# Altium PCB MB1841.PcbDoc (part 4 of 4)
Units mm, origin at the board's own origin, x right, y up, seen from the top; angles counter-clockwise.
Board outline 70 x 82.5 mm, 4 copper layers (Top Layer, Signal Layer 1, Signal Layer 2, Bottom Layer), stack 1.49 mm thick; 252 components, 169 nets, 1058 pads, 796 vias.
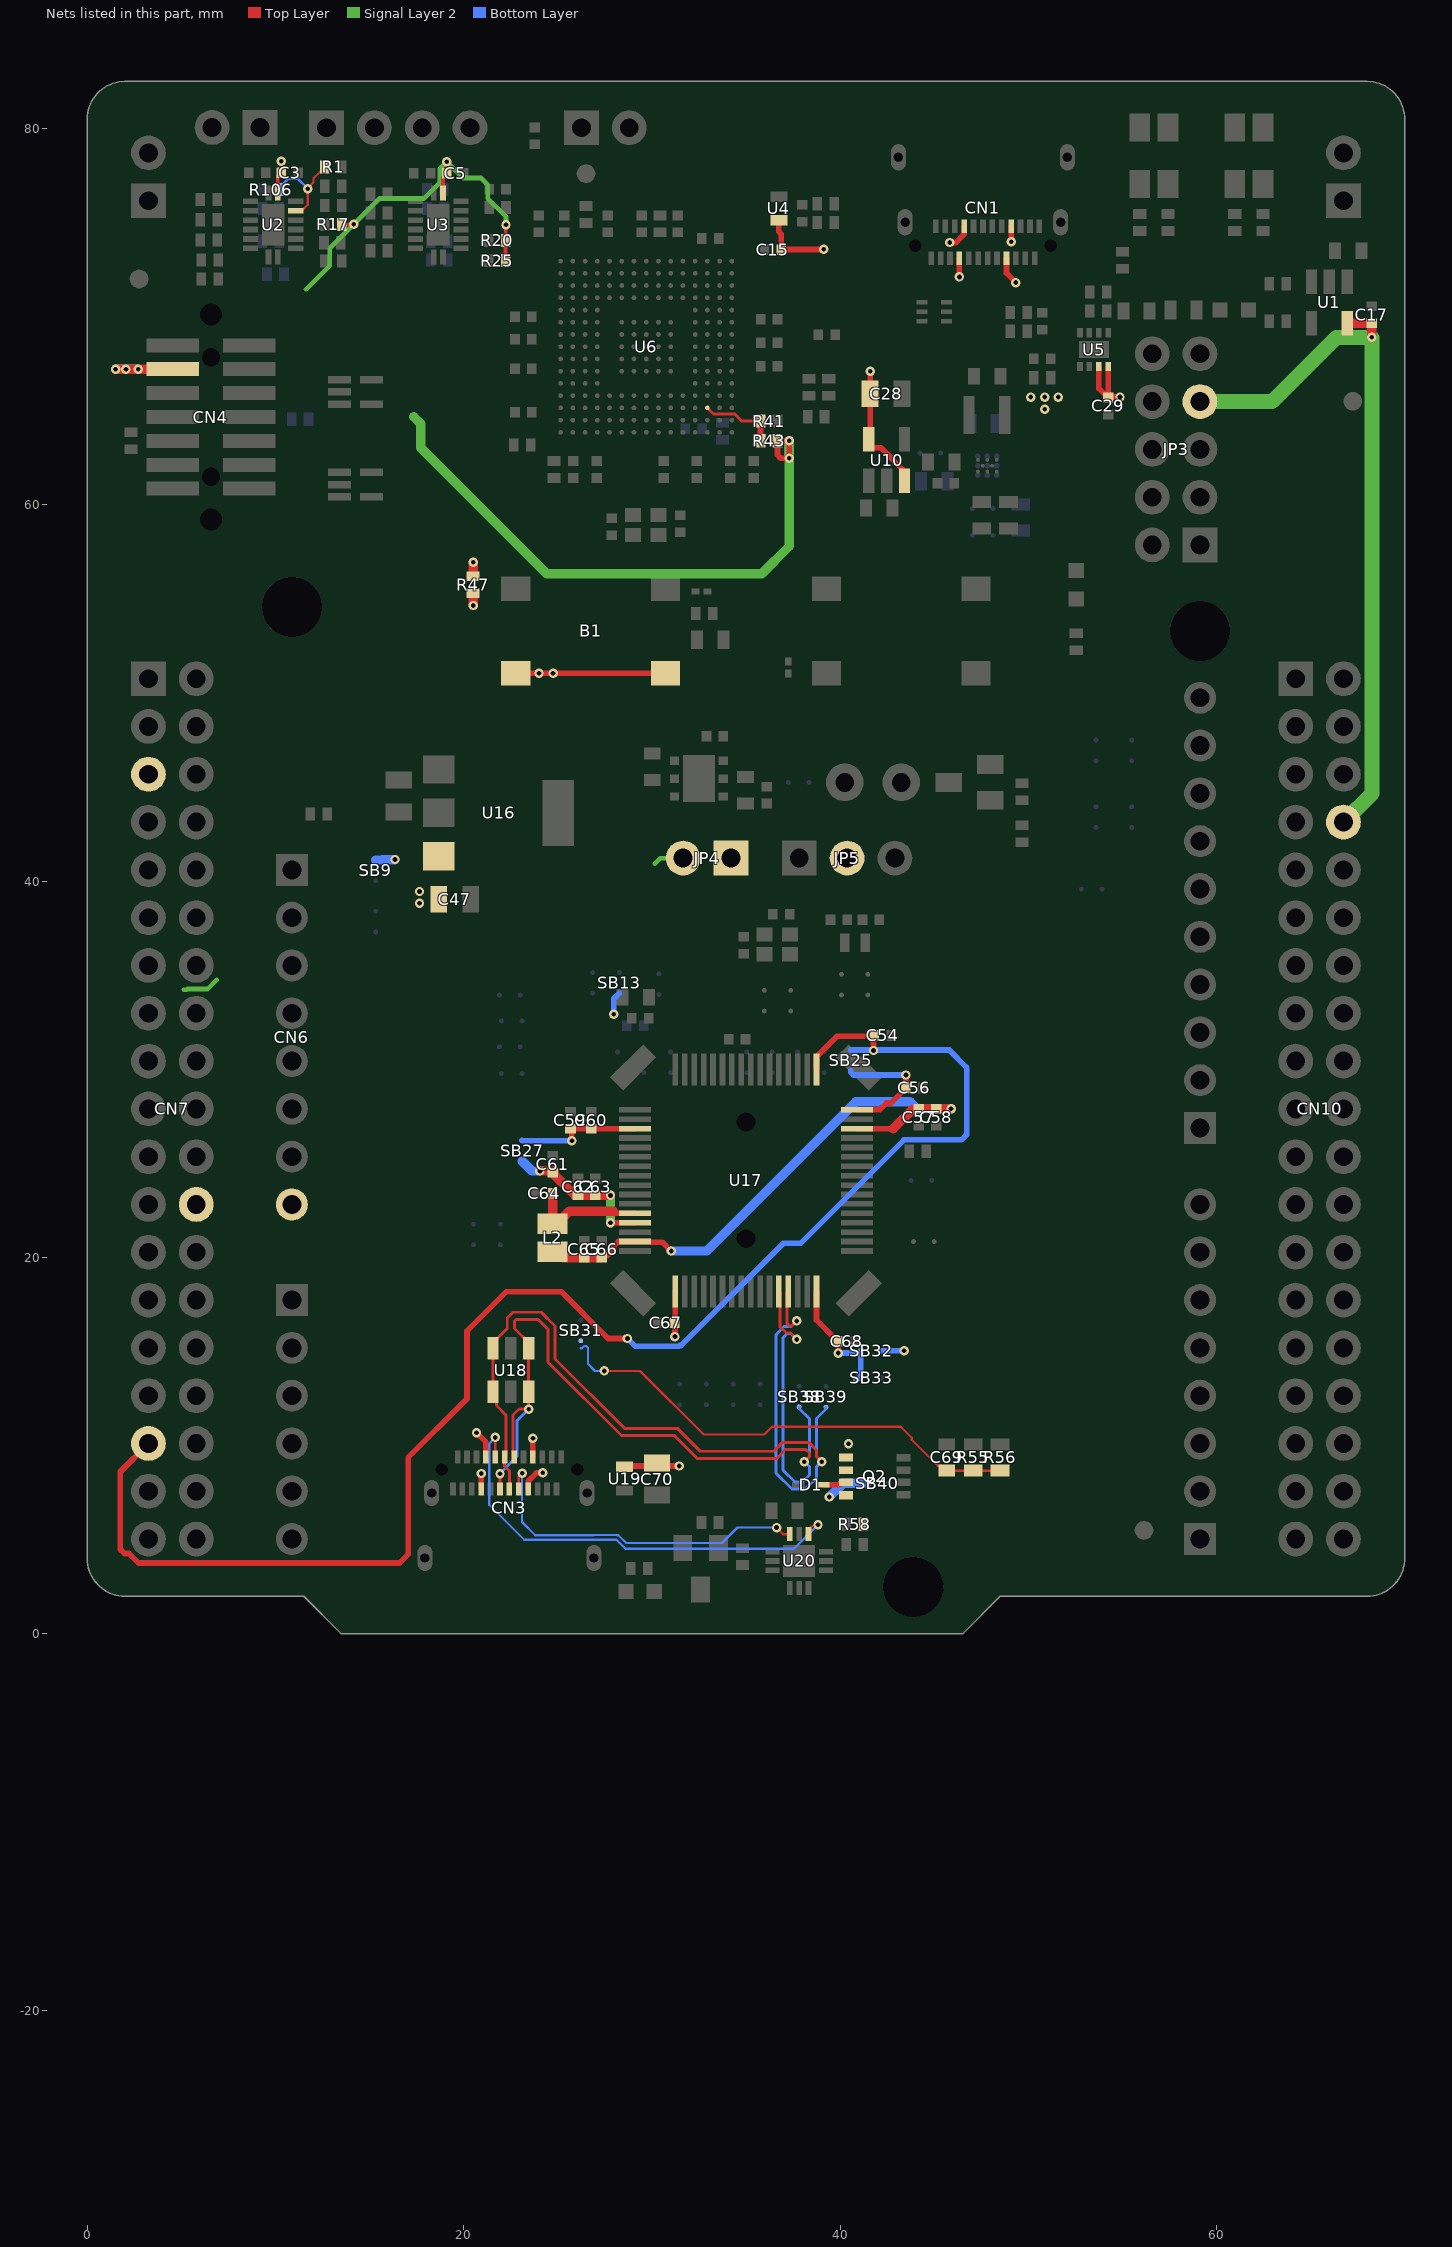
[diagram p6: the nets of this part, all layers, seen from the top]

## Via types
v1: diameter 0.5, hole 0.25, Top Layer to Bottom Layer, tented both sides, 796 vias

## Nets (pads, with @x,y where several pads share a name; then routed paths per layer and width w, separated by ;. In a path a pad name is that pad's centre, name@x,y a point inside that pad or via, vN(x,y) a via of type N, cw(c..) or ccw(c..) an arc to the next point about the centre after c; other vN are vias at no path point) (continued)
T_VCC: C3.1 C5.2 R17.2 R20.2 R25.2 R43.2 R47.2 U2.16 U3.16 | length 57.5
  Top Layer w0.2: U2.16@10.125,76.575 10.125,77.475 C3.1@10.3,77.65 v1(10.3,78.25) ; R17.2@13.525,74.9 v1(14.15,74.9) ; U3.16@18.9,76.575 18.9,77.4 19.1,77.6 C5.2@19.1,77.625 v1(19.1,78.225) ; R25.2@22.225,72.975 R20.2@22.225,74.05 22.238,74.063 22.238,74.862 v1(22.25,74.875)
  Top Layer w0.3: 36.675,62.65 R43.2@36.675,63.4 v1(37.3,63.4) v1(37.3,62.475) 36.85,62.475 36.675,62.65
  Top Layer w0.5: R47.2@20.5,56.2 v1(20.5,56.95)
  Signal Layer 2 w0.25: 11.625,71.45 12.875,72.7 12.875,73.625 v1(14.15,74.9) 15.525,76.275 17.875,76.275 18.725,77.125 18.725,77.85 v1(19.1,78.225) 19.955,77.37 20.915,77.37 21.275,77.01 21.275,76.275 22.25,75.3 v1(22.25,74.875)
  Signal Layer 2 w0.5: 17.35,64.675 17.725,64.3 17.725,63.025 24.425,56.325 35.825,56.325 37.3,57.8 v1(37.3,62.475) v1(37.3,63.4)
  Bottom Layer w0.5: v1(37.3,62.475) v1(37.3,63.4)
T_VCC_AIN: R41.1 R43.1 U6.N3 | length 4.2
  Top Layer w0.15: U6.N3@32.95,65.15 33.28,64.82 34.405,64.82 34.775,64.45 R41.1@35.775,64.45
  Top Layer w0.3: R43.1@35.775,63.4 R41.1@35.775,64.45
UCPD_CC1_C: CN3.A5 U20.7 | length 24.6
  Top Layer w0.12: CN3.A5@21.678,9.396 v1(21.678,10.441) ; U20.7@38.325,5.3 38.415,5.39 38.415,5.64 38.516,5.741 38.766,5.741 v1(38.825,5.8)
  Bottom Layer w0.12: v1(21.678,10.441) 21.361,10.124 21.361,6.858 23.216,5.004 28.118,5.004 28.597,4.525 37.55,4.525 v1(38.825,5.8)
UCPD_CC2_C: CN3.B5 U20.9 | length 18.7
  Top Layer w0.12: CN3.B5@22.928,7.696 22.928,8.358 v1(23.105,8.534) ; v1(36.625,5.65) 36.975,5.3 U20.9@37.325,5.3
  Bottom Layer w0.12: v1(23.105,8.534) 23.105,5.947 23.808,5.244 26.885,5.244 26.899,5.258 28.143,5.258 28.157,5.244 28.217,5.244 28.635,4.826 33.726,4.826 34.55,5.65 v1(36.625,5.65)
USB_FS_N: CN3.A7 CN3.B7 SB38.2 U17.44 U18.1 U18.6 | length 50.7
  Top Layer w0.155: CN3.B7@21.928,7.696 v1(21.928,8.517) ; CN3.A7@22.678,9.396 22.619,9.456 22.619,9.979 22.619,11.633 22.931,11.946 v1(23.454,11.946) U18.6@23.454,12.871 U18.1@23.454,15.171 23.454,15.471 22.695,16.23 22.695,16.622 22.786,16.713 23.96,16.713 24.47,16.203 24.47,14.455 28.381,10.544 31.192,10.544 32.411,9.325 36.633,9.325 37.108,9.8 38.175,9.8 38.369,9.606 38.369,9.431 v1(38.094,9.156) ; U17.44@36.75,18.2 36.81,18.14 36.81,16.32 37.147,15.983 37.367,15.983 v1(37.7,15.65)
  Bottom Layer w0.155: v1(21.928,8.517) 22.835,9.423 22.835,11.326 v1(23.454,11.946) ; v1(37.7,15.65) 37.4,15.95 37.184,15.95 36.975,15.741 36.975,8.7 37.6,8.075 37.994,8.075 38.369,8.45 38.369,8.749 38.369,8.881 v1(38.094,9.156) 38.369,9.431 38.369,10.021 38.369,11.431 37.843,11.957 37.843,12.045 SB38.2@37.824,12.064
USB_FS_P: CN3.A6 CN3.B6 SB39.2 U17.45 U18.3 U18.4 | length 49.7
  Top Layer w0.155: CN3.B6@22.428,7.696 22.428,8.65 22.178,8.9 CN3.A6@22.178,9.396 22.238,9.456 22.238,10.137 22.238,11.633 21.737,12.134 21.737,12.689 U18.4@21.554,12.871 U18.3@21.554,15.171 21.554,15.471 22.314,16.23 22.314,16.782 22.626,17.094 24.118,17.094 24.851,16.361 24.851,14.613 28.539,10.925 31.35,10.925 32.569,9.706 36.475,9.706 36.95,10.181 38.333,10.181 38.75,9.764 38.75,9.431 v1(39.025,9.156) ; U17.45@37.25,18.2 37.191,18.14 37.191,16.478 37.304,16.364 37.433,16.364 v1(37.7,16.631)
  Bottom Layer w0.155: v1(37.7,16.631) 37.4,16.331 37.026,16.331 36.594,15.899 36.594,8.542 37.442,7.694 38.152,7.694 38.75,8.292 38.75,8.591 38.75,8.881 v1(39.025,9.156) 38.75,9.431 38.75,10.179 38.75,11.45 39.231,11.931 39.231,12.031 SB39.2@39.25,12.05
V11: C57.2 C58.2 C65.2 C66.2 L2.1 U17.31 U17.62 | length 30.8
  Top Layer w0.3: C66.2@27.325,20 27.43,20.105 27.625,20.105 27.98,20.46 27.98,20.612 28.218,20.85 U17.31@29.1,20.85 29.888,20.85 29.926,20.812 30.563,20.812 v1(31.025,20.35) ; U17.62@40.9,26.85 42.825,26.85
  Top Layer w0.5: L2.1@24.725,20.3 24.975,20.3 25.28,19.995 26.395,19.995 C65.2@26.4,20 26.405,19.995 27.32,19.995 C66.2@27.325,20 ; 42.825,26.85 43.87,27.895 44.17,27.895 C57.2@44.175,27.9 C58.2@45.1,27.9 v1(45.9,27.9)
  Bottom Layer w0.5: v1(31.025,20.35) 32.912,20.35 40.833,28.27 43.73,28.27 44.1,27.9 v1(45.9,27.9)
VBAT: C54.2 CN7.33 SB25.2 U17.1 | length 83.6
  Top Layer w0.3: CN7.33@3.25,10.12 1.75,8.62 1.75,4.5 1.975,4.275 2.212,4.275 2.722,3.765 16.59,3.765 17.05,4.225 17.05,9.375 20.175,12.5 20.175,16.1 22.265,18.19 25.185,18.19 27.675,15.7 v1(28.7,15.7) ; U17.1@38.75,30 38.75,30.7 38.775,30.7 39.825,31.75 C54.2@41.775,31.75 ; v1(41.775,31) C54.2@41.775,31.75 ; C54.2@41.825,31.8 C54.2@41.775,31.75
  Bottom Layer w0.3: v1(28.7,15.7) 29.12,15.28 31.44,15.28 31.485,15.325 31.55,15.325 36.98,20.755 37.905,20.755 43.4,26.25 46.45,26.25 46.725,26.525 46.725,30.1 45.8,31.025 SB25.2@40.56,31.025
VBUS_C: C70.2 CN3.A4 CN3.A9 CN3.B4 CN3.B9 D1.1 Q2.5 Q2.6 Q2.7 Q2.8 R58.1 SB40.2 U19.1 | length 11.2
  Top Layer w0.3: v1(20.678,10.691) 21.178,10.191 CN3.A4@21.178,9.396 ; CN3.B9@20.928,7.696 v1(20.928,8.526) ; CN3.B4@23.428,7.696 23.428,8.123 23.865,8.56 v1(24.197,8.56) ; CN3.A9@23.678,9.396 v1(23.678,10.391) ; U19.1@28.55,8.875 28.6,8.925 v1(31.45,8.925) ; D1.1@39.125,7.925 40.025,7.925 40.15,8.05 Q2.7@40.325,8.05
  Bottom Layer w0.5: v1(39.425,7.275) 40.15,8 SB40.2@41.425,8
  other v1: 40.45,10.1
VBUS_SENSE: C69.2 R55.2 R56.1 SB31.1 | length 26
  Top Layer w0.12: v1(27.475,13.975) 29.375,13.975 32.75,10.6 35.975,10.6 36.385,11.01 43.223,11.01 43.805,10.428 43.805,10.32 45.19,8.935 45.415,8.935 C69.2@45.675,8.675 R55.2@47.075,8.675 R56.1@48.5,8.675
  Bottom Layer w0.12: 26.225,15.175 26.275,15.175 26.4,15.3 26.5,15.3 26.6,15.2 26.6,14.35 26.975,13.975 v1(27.475,13.975)
VBUS_STLK: C15.1 C17.2 C28.2 C29.2 CN1.A4 CN1.A9 CN1.B4 CN1.B9 CN10.8 JP3.7 U1.5 U4.1 U5.3 U5.4 U10.3 U10.5 | length 58
  Top Layer w0.3: U4.1@36.75,75.125 36.75,74.5 36.875,74.375 C15.1@36.875,73.55 36.887,73.562 39.112,73.562 v1(39.125,73.575) ; U10.5@41.525,63.475 41.6,63.55 C28.2@41.6,65.9 v1(41.6,67.1) ; U10.5@41.63,63.179 41.78,63.029 42.171,63.029 43.38,61.82 U10.3@43.38,61.425 ; v1(45.823,73.939) 46.154,73.939 46.592,74.377 CN1.B4@46.592,74.803 ; v1(46.342,72.108) CN1.A9@46.342,73.103 ; CN1.A4@48.842,73.103 48.842,72.308 v1(49.342,71.808) ; v1(49.092,73.973) CN1.B9@49.092,74.803 ; U5.3@53.75,67.35 53.75,66.175 54.125,65.8 C29.2@54.125,65.725 ; C29.2@54.175,65.725 v1(54.875,65.725) ; U5.4@54.25,67.35 54.25,65.85 C29.2@54.275,65.825
  Top Layer w0.5: U1.5@66.95,69.65 C17.2@68.25,69.65 ; v1(68.25,68.9) C17.2@68.25,69.65 ; C17.2@68.275,69.65 C17.2@68.25,69.65
  Signal Layer 2 w0.8: JP3.7@59.125,65.485 62.96,65.485 66.374,68.899 v1@68.249,68.899 ; CN10.8@66.75,43.14 68.275,44.665 68.275,68.875 v1(68.25,68.9)
  other v1: 50.87,65.075 50.125,65.725 50.875,65.725 51.6,65.725
VCP_RX_BP: R1.1 R106.2 U2.14 | length 5.2
  Top Layer w0.12: U2.14@11.075,75.625 11.165,75.715 11.49,75.715 11.72,75.945 v1(11.72,76.795) ; v1@11.68,76.795 12.025,77.14 12.025,77.35 12.345,77.67 12.43,77.67 12.625,77.865 R1.1@12.625,77.95
  Bottom Layer w0.12: R106.2@10.2,76.75 10.2,76.845 10.67,77.315 11.2,77.315 11.67,76.845 v1@11.71,76.845
VDD: B1.1 B1.2 CN4.3 CN7.5 JP4.1 JP5.2 R47.1 SB9.1 | length 15
  Top Layer w0.3: B1.1@22.77,51.05 v1(24,51.05) v1(24.75,51.05) ; v1@24.8,51.075 24.825,51.05 B1.2@30.72,51.05
  Top Layer w0.5: v1(1.5,67.195) v1(2.05,67.195) v1(2.7,67.195) CN4.3@4.528,67.195 ; v1(20.5,54.65) R47.1@20.5,55.3
  Signal Layer 2 w0.5: v1(1.5,67.195) v1(2.05,67.195) v1(2.7,67.195)
  Bottom Layer w0.5: v1(1.5,67.195) v1(2.05,67.195) v1(2.7,67.195) ; SB9.1@15.325,41.125 15.652,41.125 15.672,41.145 16.345,41.145 v1(16.35,41.15)
VDD_MCU: C56.2 C59.2 C60.2 C67.2 JP4.2 SB13.1 SB25.1 SB27.1 SB32.1 U17.19 U17.33 U17.64 | length 20.3
  Top Layer w0.3: v1(25.75,26.2) 25.75,26.75 25.66,26.84 26.76,26.84 26.77,26.85 C60.2@26.775,26.85 U17.19@29.1,26.85 ; v1(31.225,15.8) 31.225,16.5 C67.2@31.2,16.525 31.25,16.575 U17.33@31.25,18.2 ; U17.64@40.9,27.85 42.1,27.85 42.462,28.212 42.712,28.212 C56.2@43.38,28.88 ; C56.2@43.493,29.01 C56.2@43.493,28.993 ; v1(43.5,29.7) 43.5,29 C56.2@43.493,28.993 ; C56.2@43.38,28.88 C56.2@43.493,28.993 ; C56.2@43.38,28.88 43.388,28.88 43.493,28.985 C56.2@43.493,28.993
  Signal Layer 2 w0.25: 30.15,40.925 30.45,41.225 JP4.2@31.66,41.225
  Bottom Layer w0.3: SB27.1@23.1,26.225 23.125,26.2 v1(25.75,26.2) ; v1(27.975,32.925) 27.975,33.75 SB13.1@28.275,34.05 ; SB25.1@40.56,29.925 40.56,29.85 40.71,29.7 v1(43.5,29.7) ; SB32.1@42.2,15.05 v1(43.4,15.05)
VDDSMPS: C61.2 C62.2 C63.2 SB27.2 U17.29 | length 8.3
  Top Layer w0.3: v1@27.833,21.85 U17.29@29.1,21.85
  Top Layer w0.5: v1(24.05,24.6) 24.056,24.606 C61.2@24.79,24.606 ; C61.2@24.815,24.606 24.82,24.601 24.82,24.388 25.633,23.575 25.903,23.305 26.095,23.305 26.1,23.3 C63.2@27,23.3 27.025,23.3 v1(27.8,23.3)
  Signal Layer 2 w0.5: v1(27.8,21.85) v1(27.8,23.3)
  Bottom Layer w0.5: SB27.2@23.1,25.125 23.625,24.6 v1(24.05,24.6)
VDDUSB: C68.2 SB32.2 SB33.2 U17.48 | length 6.6
  Top Layer w0.3: U17.48@38.75,18.2 38.75,16.675 C68.2@39.745,15.68 ; v1(39.9,14.925) C68.2@39.9,15.55
  Bottom Layer w0.3: v1(39.9,14.925) 40.975,14.925 SB32.2@41.1,15.05 SB33.2@41.1,13.625 41.07,13.595 40.925,13.595 40.83,13.5
VIN: C47.2 CN6.8 CN7.24 U16.3 | length 2
  Signal Layer 2 w0.25: 5.125,34.225 5.267,34.225 5.312,34.27 6.395,34.27 6.875,34.75
  other v1: 17.65,38.825 17.65,39.45
VLX: C64.2 L2.2 U17.28 | length 5.9
  Top Layer w0.3: 27.95,22.47 28.07,22.35 U17.28@29.1,22.35
  Top Layer w0.5: L2.2@24.725,21.975 25.15,21.975 25.275,22.1 25.275,22.132 25.613,22.47 27.95,22.47 ; L2.2@24.725,22.2 C64.2@24.725,23.425
pads on no net: CN1.0 CN1.A2 CN1.A3 CN1.A8 CN1.A10 CN1.A11 CN1.B2 CN1.B3 CN1.B8 CN1.B10 CN1.B11 CN3.0 CN3.A2 CN3.A3 CN3.A8 CN3.A10 CN3.A11 CN3.B2 CN3.B3 CN3.B8 CN3.B10 CN3.B11 CN4.0 CN4.1 CN4.2 CN7.9 CN7.10 CN7.11 CN7.21 CN7.26 CN10.1 CN10.6 CN10.10 CN10.16 CN10.18 CN10.34 CN10.38 Designator1.1 Designator2.1 Designator3.1 U6.A1 U6.A2 U6.A3 U6.A4 U6.A5 U6.A8 U6.A9 U6.A11 U6.A12 U6.A13 U6.B1 U6.B2 U6.B3 U6.B4 U6.B5 U6.B6 U6.B7 U6.B8 U6.B9 U6.B10 U6.B11 U6.B12 U6.B13 U6.B14 U6.B15 U6.C2 U6.C3 U6.C12 U6.C13 U6.C14 U6.C15 U6.D1 U6.D2 U6.D3 U6.D11 U6.D13 U6.D14 U6.E1 U6.E2 U6.E3 U6.E4 U6.E12 U6.E13 U6.E14 U6.E15 U6.F1 U6.F4 U6.F14 U6.G4 U6.G14 U6.G15 U6.H2 U6.H3 U6.H4 U6.H14 U6.J3 U6.J4 U6.K1 U6.K2 U6.K3 U6.K12 U6.K13 U6.K14 U6.K15 U6.L1 U6.L12 U6.L13 U6.L14 U6.L15 U6.M2 U6.M3 U6.M4 U6.M7 U6.M12 U6.M13 U6.M14 U6.M15 U6.N2 U6.N4 U6.N6 U6.N7 U6.N11 U6.N13 U6.N14 U6.N15 U6.P2 U6.P4 U6.P5 U6.P6 U6.P7 U6.P8 U6.P9 U6.P10 U6.P11 U6.P12 U6.P13 U6.P14 U6.P15 U6.R2 U6.R6 U6.R7 U6.R8 U6.R9 U6.R10 U6.R11 U6.R12 U6.R13 U8.4 U10.4 U11.4 U12.E1 U15.3 U15.5 U17.0 U18.5 U22.C1

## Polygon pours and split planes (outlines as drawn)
GND on Top Layer "GND" (solid, remove dead copper, pour order 138): 68.45,84.375 70.175,82.65 70.175,2.125 66.85,-1.2 0.925,-1.2 -1.825,1.55 -1.825,82.05 0.5,84.375
5V_UCPD on Top Layer "NO_FT" (solid, pour order 125): 44.276,6.9 44.6,7.224 44.613,8.863 44.375,9.1 43.15,9.1 42.8,8.75 42.8,7 42.9,6.9
VBUS_C on Top Layer "NO_FT" (solid, pour order 124): 41.91,10.4 42.35,9.96 42.35,6.325 41.5,5.475 40.975,5.475 40.775,5.675 40.775,6.225 40.35,6.65 39.325,6.65 38.775,7.2 38.775,8.075 38.925,8.225 39.8,8.225 39.95,8.375 39.95,10.3 40.05,10.4
5V on Top Layer "NO_FT" (solid, pour order 113): 34.125,46.875 33.61,46.875 33.5,47 33.5,48.3 34.05,48.85 34.65,48.85 34.849,48.651 34.849,47.599
VIN on Top Layer "NO_FT" (solid, remove dead copper, pour order 8): 20.5,42.125 20.625,42 20.625,38.025 20.35,37.75 17.1,37.75 16.75,38.1 16.75,41.85 17.025,42.125
GND on Top Layer "NO_FT" (solid, remove dead copper, pour order 6): 20.625,45.025 20.35,44.75 16.15,44.75 15.875,45.025 15.875,48.2 16.275,48.6 20.275,48.6 20.625,48.25
5V_VIN on Top Layer "NO_FT" (solid, remove dead copper, pour order 4): 12.725,42.375 12.35,42.75 12.35,44.025 12.825,44.5 16.3,44.5 20.4,44.5 21,45.1 21,46.925 21.425,47.35 26.8,47.35 27.3,46.85 27.3,40.7 26.725,40.125 21.7,40.125 21.225,40.6 21.225,41.825 20.675,42.375
NetC44_2 on Top Layer "NO_FT" (solid, pour order 121): 33.3,43.9 33.85,43.35 37.625,43.35 38.05,43.775 38.05,44.4 37.725,44.725 34.45,44.725 34.225,44.95 33.375,44.95 33.3,44.875
5V_SMPS_IN on Top Layer "5V_SMPS_IN" (solid, pour order 126): 47.45,62.4 46.45,63.4 46.05,63.4 45.675,63.025 45.675,59.025 46.4,58.3 47.95,58.3 48.075,58.425 48.075,59.2 47.925,59.35 47.15,59.35 46.595,59.905 46.595,61.789 46.806,62 47.575,62
5V_VIN on Top Layer "5V_VIN_L01_P130" (solid, remove dead copper, pour order 130): 58.598,59.175 57.513,58.09 51.185,58.09 50.1,59.175 49.525,59.75 49.525,62.275 49.775,62.525 53.578,62.525 54.651,61.453 59.502,61.453 60.02,60.935 60.02,60.02 59.175,59.175
E5V on Top Layer "E5V_L01_P136" (solid, remove dead copper, pour order 136): 53.583,62.8 54.93,61.453 59.7,61.453 60.655,62.408 60.655,63.652 60.376,63.932 55.753,63.932 54.635,65.05 53.3,65.05 52.775,64.525 49.775,64.525 49.5,64.25 49.5,63.05 49.75,62.8
VBUS_STLK on Top Layer "VBUS_STLK_L01_P137" (solid, remove dead copper, pour order 137): 60.449,67.125 57.485,67.125 56.002,68.608 50.358,68.608 49.75,68 49.75,65.5 50.45,64.8 52.55,64.8 53.167,65.417 54.649,65.417 56.007,64.059 60.147,64.059 60.875,64.787 60.875,66.699
GND on Top Layer "GND_L01_P002" (solid, remove dead copper, pour order 2): 31.675,77.625 33.25,76.05 33.25,71.275 34.15,70.375 38.15,70.375 40,72.225 40,82.5 30.65,82.5 30.65,78.675 31.675,77.65
5V_STLK on Top Layer "5V_STLK_L01_P078" (solid, remove dead copper, pour order 78): 61.5,74 61.75,74.25 66.5,74.25 66.5,73 63.5,73 63.5,72.5 54.175,72.5 54.175,74
GND on Bottom Layer "GND" (solid, remove dead copper, pour order 134): 69.929,84.391 71.654,82.666 71.654,2.141 68.329,-1.184 2.404,-1.184 -0.346,1.566 -0.346,82.066 1.979,84.391
5V_SMPS_IN on Bottom Layer "5V_SMPS_IN" (solid, pour order 127): 46.405,63.42 46.405,63.625 46.255,63.775 45.2,63.775 45.1,63.675 45.1,63.375 45.25,63.225 45.25,62.85 44.95,62.55 44.65,62.55 44.225,62.125 44.075,62.125 43.775,61.825 43.775,60.73 43.905,60.6 44.745,60.6 45,60.855 45,61.875 45.25,62.125 46.925,62.125 47.025,62.225 47.025,62.8
VBUS_C on Bottom Layer "VBUS_C" (solid, remove dead copper, pour order 133): 40.275,10.425 40.951,10.424 42.175,9.2 42.175,8.5 41.675,8 42.175,7.5 42.175,7.075 41.951,6.851 39.424,6.851 39.175,7.1 39.175,7.375 40.075,8.275 40.075,10.225
5V_UCPD on Bottom Layer "5V_UCPD" (solid, remove dead copper, pour order 132): 44.289,6.913 44.6,7.224 44.6,8.85 44.35,9.1 43.025,9.1 42.425,8.5 42.425,7.5 43.012,6.913
NetR63_2 on Bottom Layer "NetR46_2" (solid, pour order 131): 45.45,62.05 46.95,62.05 47.15,62.25 47.4,62.25 47.525,62.125 47.525,60.925 47.2,60.6 47.2,59.375 47.125,59.3 45.775,59.3 45.225,59.85 45.225,61.825
VDD on Bottom Layer "VDD" (solid, pour order 123): 23.275,51.3 24,52.025 30.725,52.025 35.925,46.825 35.925,40.298 35.127,39.5 33.175,39.5 32.5,40.175 32.5,41.725 30.55,43.675 30.55,47.95 28.55,49.95 23.75,49.95 23.275,50.425
5V_STLK on Bottom Layer "g" (solid, remove dead copper, pour order 110): 67.75,73 66.5,74.25 63.75,74.25 63.25,73.75 63.25,62.475 60.625,59.85 58.3,59.85 58.3,56.925 58.575,56.65 60.163,56.65 63.65,56.65 67.75,60.75
3V3 on Bottom Layer "3V3_L04_P080" (solid, remove dead copper, pour order 80): 40.951,54.1 36.438,49.51 36.437,40.037 37.4,39.075 41.275,39.075 42.15,39.95 42.15,48.425 43.575,49.85 53.95,49.85 54.8,50.7 54.8,52.875 53.575,54.1
5V_VIN on Bottom Layer "5V_VIN_L04_P042" (solid, remove dead copper, pour order 42): 58.598,59.175 57.513,58.09 51.185,58.09 50.1,59.175 49.525,59.75 49.525,62.275 49.775,62.525 53.578,62.525 54.651,61.453 59.502,61.453 60.02,60.935 60.02,60.02 59.175,59.175
NetC44_2 on Bottom Layer "NO_FT" (solid, pour order 14): 36.437,46.216 37.659,46.216 38.05,45.825 38.05,44.4 38.05,43.775 37.837,43.562 37.213,43.562 36.437,44.338
5V_VIN on Bottom Layer "5V_VIN_L04_P040" (solid, remove dead copper, pour order 40): 21.5,47.5 20.375,46.375 20.375,40.47 20.72,40.125 26.575,40.125 26.92,40.47 26.92,47.23 26.65,47.5
VBUS_STLK on Bottom Layer "VBUS_STLK_L04_P048" (solid, remove dead copper, pour order 48): 60.449,67.125 57.485,67.125 56.002,68.608 50.358,68.608 49.75,68 49.75,65.5 50.45,64.8 52.55,64.8 53.167,65.417 54.649,65.417 56.007,64.059 60.147,64.059 60.875,64.787 60.875,66.699
E5V on Bottom Layer "E5V_L04_P050" (solid, remove dead copper, pour order 50): 53.583,62.8 54.93,61.453 59.7,61.453 60.605,62.358 60.605,63.703 60.376,63.932 55.753,63.932 54.635,65.05 53.3,65.05 52.775,64.525 49.775,64.525 49.5,64.25 49.5,63.05 49.75,62.8
GND on Signal Layer 2 "GND" (solid, remove dead copper, pour order 135): 68.45,84.375 70.175,82.65 70.175,2.125 66.85,-1.2 0.925,-1.2 -1.825,1.55 -1.825,82.05 0.5,84.375
5V on Signal Layer 2 "5V_L03_P129" (solid, remove dead copper, pour order 129): 30,46 30.5,45.5 37.109,45.5 39.625,42.9 43.625,42.9 45.65,40.825 45.65,26.525 43,23.875 43,19.375 43,18.05 45.075,15.975 45.075,14.4 41,10.325 41,8 38.425,5.425 18.7,5.425 16.8,7.325 16.8,29.185 13.958,32.027 5.727,32.027 4.825,31.125 4.825,29.225 5.325,28.725 10.5,28.725 12.5,26.725 12.5,5.55 16.875,1.175 40.675,1.175 45.625,6.125 45.637,9.188 53.725,17.275 53.725,33 55.75,35.025 55.75,55.025 58.15,57.425 58.15,68.025 57.62,68.575 57.625,69.25 57.625,69.95 57.325,70.25 53.1,70.25 52.9,70.05 52.925,70.025 52.925,57.556 50.65,55.281 50.65,49.15 50.505,49 31.225,49 30,47.775
VDD on Signal Layer 2 "VDD" (solid, pour order 128): 33.069,36.375 40.851,36.375 42.113,37.747 42.113,42.8 39.25,42.8 39.25,39.9 38.975,39.625 36.3,39.625 35.85,40.075 35.85,42.8 33.071,42.8 33.069,42.389
3V3 on Signal Layer 2 "3V3" (solid, pour order 122): 26.95,44.55 27,44.5 30.25,44.5 31,45.25 37.2,45.25 39.125,43.325 39.125,40.15 38.76,39.785 36.59,39.785 36.225,40.15 36.225,42.7 36.05,42.875 31.55,42.875 28.121,39.446 28.121,34.421 27.425,33.725 27.425,32.65 24.9,30.125 24.9,22.075 32.675,14.3 40.014,14.3 40.164,14.45 43.7,14.45 44.025,14.125 44.025,13.525 41.125,10.625 39.275,10.625 36.638,7.988 33.312,7.988 31.6,9.7 18.4,9.7 17,11.1 17,29.075 14.025,32.05 4.975,32.05 4.7,32.325 4.7,33.44 5.51,34.25 11.675,34.25 14.925,37.5 18.767,37.5 19.9,37.5
E5V on Signal Layer 2 "E5V_L03_P115" (solid, remove dead copper, pour order 115): 24.5,50.25 25.2,50.95 25.2,53.375 26.225,54.4 37.275,54.4 47.475,64.6 49.598,64.6 52.026,64.599 52.25,64.375 52.25,62.5 52,62.25 49.5,62.25 48.775,61.525 48.775,59.7 40.575,51.5 27.95,51.5 24.3,47.85 20.925,47.85 18.375,45.3 15.925,45.3 13.025,42.4 6.225,42.4 4.625,44 4.625,46.65 8.225,50.25
5V_VIN on Signal Layer 2 "5V_VIN_L03_P020" (solid, remove dead copper, pour order 20): 49.375,61.4 49.85,61.875 51.925,61.875 52.35,61.45 52.35,58.05 52.35,57.525 50.35,55.525 50.35,49.325 49.575,48.538 30.663,48.538 25.15,43.025 20.775,43.025 20.412,43.388 20.412,46.387 21.4,47.375 24.1,47.375 28.075,51.35 41.2,51.35 49.375,59.525
T_VCC on Signal Layer 2 "T_VCC_L03_P062" (solid, remove dead copper, pour order 62): 8,66.75 8,65 13,60 17,60 22.456,54.544 26.219,54.544 37.044,54.544 38.25,55.75 38.25,63.375 37.801,63.824 37.099,63.824 36.675,63.4 36.675,58.437 35.519,57.281 26.419,57.281 11.325,72.375 6.225,72.375 4.826,73.774 4.826,75.326 8.069,78.569 9.711,78.569 9.8,78.48 9.8,77.8 9.95,77.65 10.75,77.65 10.806,77.706 10.806,78.468 9.949,79.325 7.325,79.325 3.95,75.95 3.95,70.8 6,68.75
GND on Signal Layer 2 "GND_L03_P044" (solid, remove dead copper, pour order 44): 56.825,82.35 58.15,81.025 58.15,79.375 58.6,78.925 62,78.925 69.425,71.5 69.9,71.5 69.9,81.45 69,82.35
VBUS_STLK on Signal Layer 2 "VBUS_STLK_L03_P026" (solid, remove dead copper, pour order 26): 64.675,63.043 63.227,64.491 58.674,64.491 58.037,65.127 58.037,70.188 57.575,70.65 52.75,70.65 52.375,70.275 52.375,65.15 52.025,64.8 43.15,64.8 38.75,69.2 38.75,73.875 41.075,76.2 41.425,76.55 63.775,76.55 65.453,74.873 66.652,74.873 68.875,72.65 68.875,71.45 68.875,42.15 68.275,41.55 65.825,41.55 64.675,42.7
3V3_STLK on Signal Layer 2 "3V3_STLK_L03_P024" (solid, remove dead copper, pour order 24): 11.027,77.814 10.763,77.55 9.925,77.55 9.75,77.725 9.75,78.45 9.7,78.5 8.25,78.5 5,75.25 5,72.75 5.25,72.5 11.275,72.5 26.35,57.425 35.375,57.425 36.35,58.4 36.35,65.925 36.65,66.225 36.65,69.475 38.4,71.225 38.4,73.925 41.175,76.7 59.7,76.7 60.5,77.5 60.5,80.5 59.75,81.25 39.95,81.25 36.25,77.55 36.25,76 34.75,74.5 32.75,74.5 30.675,76.575 30.675,80.75 30.05,81.375 11.822,81.398 7.948,81.398 7.726,81.176 7.726,79.526 7.927,79.325 10.165,79.325 11.027,78.463
VIN on Signal Layer 2 "VIN" (solid, pour order 119): 18.64,37.965 18.025,37.35 14.7,37.35 11.575,34.225 5.775,34.225 4.65,33.1 4.65,25.25 5.45,24.45 12.15,24.45 12.425,24.175 12.425,21.875 11.645,21.095 1.68,21.095 1.2,21.575 1.2,36.01 4.265,39.075 15.575,39.075 16.55,40.05 18.395,40.05 18.64,39.805
VDD on Signal Layer 2 "VDDIO1_4_L01_P-001" (solid, pour order 16): 1.25,58.75 1.25,67.5 1.5,67.75 3,67.75 5.75,65 5.75,60.25 11,55 23,55 25.25,52.75 25.25,51 24.75,50.5 8,50.5 6.75,49.25 4.5,47 4.5,44 6.25,42.25 16.25,42.25 16.75,41.75 16.75,40.5 15.25,39 2,39 1.25,39.75
E5V on Signal Layer 2 "E5V_L03_P058" (solid, remove dead copper, pour order 58): 49.6,64.6 49.375,64.375 49.375,62.875 49.5,62.75 52.1,62.75 52.25,62.9 52.25,64.375 52.025,64.6
VBUS_C on Signal Layer 2 "USB_VBUS" (solid, pour order 116): 21.25,5.525 21.225,5.5 18.75,5.5 17,7.25 17,12.75 25,12.75 28.25,9.5 29.75,9.5 31.45,9.5 33.162,7.787 36.537,7.787 39.175,10.425 40.75,10.425 40.75,8.05 38.225,5.525
VDD_MCU on Signal Layer 2 "VDD_MCU" (solid, pour order 118): 43.943,28.168 43.943,29.906 43.674,30.175 35.95,30.175 33.275,32.85 33.275,42.183 32.783,42.675 31.425,42.675 28.325,39.575 28.325,34.5 25.075,31.25 25.075,21.9 32.475,14.5 43.575,14.5 43.775,14.7 43.775,15.577 43.492,15.861 41.164,15.861 40.55,16.45 40.55,24.775
GND on Signal Layer 1 "GND" (solid, remove dead copper, pour order 120): 68.45,84.375 70.175,82.65 70.175,2.125 66.85,-1.2 0.925,-1.2 -1.825,1.55 -1.825,82.05 0.5,84.375

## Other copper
Top Layer:
  pour cut-out: 22.216,70.344 22.216,61.884 23.184,60.916 27.609,60.916 27.65,60.957 27.65,62.45 24.5,62.45 23.525,63.425 23.55,63.45 23.55,73.5 24.75,74.7 31.825,74.7 32.116,74.991 32.116,75.884 30.376,75.884 30.36,75.9 25.275,75.9 24.35,74.975 21.446,74.975 20.725,74.254 20.725,71.25 21.625,70.35 21.725,70.35
  pour cut-out: 31.054,60.916 35.959,60.916 37.184,62.141 37.184,69.674 37.108,69.75 35.95,69.75 35.95,63.025 35.05,62.125 31.025,62.125
  pour cut-out: 35.975,32.8 35.225,32.8 34.85,33.175 34.85,34.7 34.175,35.375 34.175,37.675 35.365,38.865 37.86,38.865 38.451,38.274 38.852,38.675 42.59,38.675 42.9,38.365 42.9,33.325 42.35,32.775 40.6,32.775 39.875,33.5 36.675,33.5
  pour cut-out: 4.8,68.975 4.875,69.05 7.85,69.05 8.55,68.35 9.913,68.35 10.022,68.241 10.022,67.765 10.265,67.765 10.275,67.775 12.5,67.775 13.85,66.425 13.85,63.466 13.534,63.15 10.5,63.15 10.126,62.776 10.126,61.036 9.465,60.375 2.975,60.375 2.75,60.6 2.75,68.75 3,69
  pour cut-out: 32.5,70.25 27,70.25 27,66.25 32.5,66.25
  text "1" at 46.875,5.2 h2.5
  text ".Layer_Name" at -0.272,-22.558 h3
  text ".GTL" at 41.423,-22.558 h3
Signal Layer 1:
  text "2" at 48.625,5.2 h2.5
  text ".Layer_Name" at -0.272,-22.558 h3
  text ".G1" at 41.423,-22.558 h3
Signal Layer 2:
  text "3" at 51.625,5.2 h2.5
  text ".Layer_Name" at -0.272,-22.558 h3
  text ".G2" at 41.423,-22.558 h3
Bottom Layer:
  pour cut-out: 16.825,36.8 15.125,36.8 13.825,35.5 13.825,27.95 14.35,27.425 14.35,17.1 15.125,16.325 15.925,16.325 16.275,16.675 16.275,18.25 17.025,19 17.025,20.9 17.65,21.525 17.65,36.075 17.225,36.5
  pour cut-out: 25.925,34.375 25.925,38.45 27.25,39.775 28.511,39.775 29.875,38.411 29.875,33.2 28.785,32.11 26.673,32.11 25.898,32.885
  text "4" at 53.625,5.2 h2.5
  text ".GBL" at 30.22,-22.59 h3
  text ".Layer_Name" at 71.534,-22.59 h3
Multi-Layer:
  pour cut-out: 46.125,7.4 46.125,4.4 54.625,4.4 54.625,7.4

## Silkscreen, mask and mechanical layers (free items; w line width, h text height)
Top Overlay:
  circle w0.3: c31.583,38.107 r1.485
  rectangle: 29.508,37.957 30.108,38.232
  region: 33.658,38.232 33.058,38.232 33.058,37.957 33.658,37.957
  text "STLK RST" at 2.337,81.432 h1.5
  text "BOOT" at 30.556,80.442 h1.5
  text "USB STLK" at 35.461,80.183 h1.5
  text "PWR" at 54.35,78.125 h1.5 r90
  text "COM" at 59.75,78.125 h1.5 r90
  text "USB USER" at 60.8,67.25 h1.5
  text "CHGR" at 60.875,64.9 h1.5
  text "E5V" at 60.775,62.325 h1.5
  text "VIN 5V" at 60.751,59.797 h1.5
  text "STLK" at 60.775,57.325 h1.5
  text "DEBUG IN" at 3.8,56.8 h1.5
  text "5V_SEL" at 55.35,55.15 h1.5
  text "SCL" at 54.869,49.843 h1.14
  text "USER" at 24.25,48.625 h1.5
  text "RESET" at 40.425,48.55 h1.5
  text "D15" at 54.379,48.417 h1.02
  text "L" at 13.075,48.375 h13
  text "SDA" at 54.779,47.325 h1.14
  text "3V3" at 38.2,46.625 h1.5
  text "1V8" at 42.2,46.625 h1.5
  text "D14" at 54.333,46.029 h1.02
  text "E5V" at 7.47,45.115 h1.5
  text "AVDD" at 54.204,44.12 h0.84
  text "GND" at 7.314,42.632 h1.5
  text "GND" at 54.115,41.457 h1.02
  text "SCK" at 54.783,40.06 h1.14
  text "D13" at 54.672,38.917 h0.89
  text "IDD" at 27.94,38.887 h1.5
  text "MISO" at 54.345,37.698 h1.14
  text "IOREF" at 12.394,37.552 h1.5
  text "A" at 30.858,37.382 h2.5
  text "D12" at 54.672,36.606 h0.89
  text "PWM" at 54.498,35.279 h1.14
  text "NRST" at 12.394,34.758 h1.5
  text "MOSI" at 54.396,34.39 h1.14
  text "D11" at 55.058,33.323 h0.89
  text "3V3" at 12.394,32.472 h1.5
  text "PWM" at 54.498,32.231 h1.14
  text "CS" at 55.524,31.291 h1.14
  text "H" at 17.577,30.658 h15
  text "D10" at 54.701,30.248 h0.89
  text "5V" at 12.394,29.678 h1.5
  text "PWM" at 54.499,28.956 h1.14
  text "D9" at 55.349,27.891 h0.89
  text "GND" at 12.25,27.275 h1.5
  text "IO" at 55.834,26.684 h1.14
  text "D8" at 55.134,25.459 h1.02
  text "GND" at 12.394,24.598 h1.5
  text "IO" at 55.731,22.959 h1.14
  text "VIN" at 12.394,22.058 h1.5
  text "D7" at 55.109,21.666 h1.02
  text "PWM" at 54.475,20.291 h1.14
  text "D6" at 55.156,18.926 h1.02
  text "PWM" at 54.458,17.573 h1.14
  text "A0" at 12.394,16.978 h1.5
  text "D5" at 55.091,16.379 h1.02
  text "IO" at 55.828,15.153 h1.14
  text "A1" at 12.394,14.438 h1.5
  text "D4" at 55.216,13.934 h1.02
  text "J" at 42.2,13.75 h15
  text "PWM" at 54.458,12.903 h1.14
  text "MB1841E" at 41.725,12.65 h2.5
  text "A2" at 12.394,11.898 h1.5
  text "D3" at 55.118,11.709 h1.02
  text "IO" at 55.88,10.617 h1.14
  text "D2" at 55.194,9.398 h1.02
  text "A3" at 12.394,9.358 h1.5
  text "TX" at 55.575,8.407 h1.14
  text "D1" at 55.296,7.29 h1.02
  text "A4" at 12.394,6.818 h1.5
  text "A5" at 12.394,4.278 h1.5
  text "RX" at 56.032,3.226 h1.14
  text "D0" at 55.855,2.134 h1.02
  text "USB / USER" at 12.218,1.098 h1.5
  text "VBUS" at 27.9,0.375 h1.5
  text ".Layer_Name" at -0.272,-22.558 h3
  text ".GTO" at 41.423,-22.558 h3
Bottom Overlay:
  drawing of 306 lines, arcs and shapes, not listed
  text "CN12" at 68.7,80.375 h1.2
  text "1" at 24.525,79.5 h1.5
  text "JP1" at 8.433,77.419 h1.2
  text "1" at 12.319,77.394 h1.5
  text "1" at 9.97,77.35 h1.5
  text "RESERVED" at 20.32,77.28 h1.5
  text "CN2" at 24.275,77.165 h1.2
  text "JP2" at 28.75,77.075 h1.2
  text "CN11" at 0.838,76.276 h1.2 r270
  text "1" at 65.075,75.492 h1.5
  text "1" at 5.525,75.417 h1.5
  text "JP3" at 59.5,70.2 h1.2
  text "C" at 19.25,67.5 h8
  text "F" at 19.25,62 h9
  text "I" at 26.475,58.075 h10
  text "1" at 61.245,57.262 h1.5
  text "G" at 19.5,56.5 h8
  text "CN7" at 6.25,52.375 h1.2
  text "CN10" at 67.675,52.3 h1.2
  text "S" at 19,50.75 h8
  text "1" at 1.98,50.252 h1.5
  text "2" at 68.93,50.127 h1.5
  text "10" at 62.201,49.059 h1.5
  text "3" at 1.98,47.712 h1.5
  text "4" at 68.93,47.587 h1.5
  text "9" at 61.312,46.519 h1.5
  text "5" at 1.98,45.172 h1.5
  text "6" at 68.93,45.047 h1.5
  text "E" at 19.456,44.45 h10
  text "8" at 61.312,43.979 h1.5
  text "7" at 1.98,42.632 h1.5
  text "8" at 68.93,42.507 h1.5
  text "CN6" at 12.675,42.35 h1.2
  text "7" at 61.312,41.439 h1.5
  text "JP4" at 29.625,40.675 h1.2
  text "JP5" at 47.925,40.6 h1.2
  text "9" at 1.98,40.092 h1.5
  text "1" at 9.6,40.092 h1.5
  text "10" at 69.692,39.967 h1.5
  text "1" at 37.2,39.025 h1.5 r270
  text "1" at 33.65,38.92 h1.5 r270
  text "6" at 61.312,38.899 h1.5
  text "11" at 1.98,37.552 h1.5
  text "2" at 9.6,37.552 h1.5
  text "12" at 69.692,37.427 h1.5
  text "5" at 61.312,36.359 h1.5
  text "13" at 1.98,35.012 h1.5
  text "3" at 9.6,35.012 h1.5
  text "14" at 69.692,34.887 h1.5
  text "CN5" at 56.4,34.15 h1.2 r270
  text "4" at 61.312,33.819 h1.5
  text "15" at 1.98,32.472 h1.5
  text "4" at 9.6,32.472 h1.5
  text "16" at 69.692,32.347 h1.5
  text "3" at 61.312,31.279 h1.5
  text "17" at 1.98,29.932 h1.5
  text "5" at 9.6,29.932 h1.5
  text "18" at 69.692,29.807 h1.5
  text "2" at 61.312,28.739 h1.5
  text "19" at 1.98,27.392 h1.5
  text "6" at 9.6,27.392 h1.5
  text "20" at 69.819,27.267 h1.5
  text "1" at 60.931,26.199 h1.5
  text "21" at 1.98,24.852 h1.5
  text "7" at 9.6,24.852 h1.5
  text "22" at 69.819,24.727 h1.5
  text "23" at 1.98,22.312 h1.5
  text "8" at 9.6,22.312 h1.5
  text "24" at 69.819,22.187 h1.5
  text "8" at 61.312,22.135 h1.5
  text "25" at 1.98,19.772 h1.5
  text "26" at 69.819,19.647 h1.5
  text "7" at 61.312,19.595 h1.5
  text "CN8" at 12.525,19.525 h1.2
  text "27" at 1.98,17.232 h1.5
  text "1" at 9.6,17.232 h1.5
  text "28" at 69.819,17.107 h1.5
  text "6" at 61.312,17.055 h1.5
  text "29" at 1.98,14.692 h1.5
  text "2" at 9.6,14.692 h1.5
  text "30" at 69.819,14.567 h1.5
  text "5" at 61.312,14.515 h1.5
  text "31" at 1.98,12.152 h1.5
  text "3" at 9.6,12.152 h1.5
  text "32" at 69.819,12.027 h1.5
  text "4" at 61.312,11.975 h1.5
  text "CN9" at 56.25,11.675 h1.2 r270
  text "33" at 1.98,9.612 h1.5
  text "4" at 9.6,9.612 h1.5
  text "34" at 69.819,9.487 h1.5
  text "3" at 61.312,9.435 h1.5
  text "35" at 1.98,7.072 h1.5
  text "5" at 9.6,7.072 h1.5
  text "36" at 69.819,6.947 h1.5
  text "2" at 61.312,6.895 h1.5
  text "37" at 1.98,4.532 h1.5
  text "6" at 9.6,4.532 h1.5
  text "38" at 69.819,4.407 h1.5
  text "1" at 60.931,4.355 h1.5
  text ".GBO" at 30.22,-22.59 h3
  text ".Layer_Name" at 71.534,-22.59 h3
Top Paste:
  text ".Layer_Name" at -0.299,-22.548 h3
  text ".GTP" at 41.396,-22.548 h3
Bottom Paste:
  text ".GBP" at 30.111,-22.575 h3
  text ".Layer_Name" at 71.425,-22.575 h3
Top Solder:
  rectangle: 46.375,4.7 54.375,7.2
  text ".Layer_Name" at -0.274,-22.623 h3
  text ".GTS" at 41.421,-22.623 h3
Bottom Solder:
  rectangle: 46.375,4.7 54.375,7.2
  text ".GBS" at 30.136,-22.65 h3
  text ".Layer_Name" at 71.45,-22.65 h3
M1-Board Shape:
  lines w0.1: 48.5,2 68,2 ccw(c68,4) 70,4 70,58 70,80.5 ; 48.5,2 48.5,2 ; 48.5,2 46.5,0 13.5,0 11.5,2 2,2 cw(c2,4) 0,4 0,58 0,80.5 cw(c2,80.5) 2,82.5 68,82.5 cw(c68,80.5) 70,80.5 ; 70,80.5 70,80.5
M2-Board Dimensions:
  text ".Layer_Name" at -0.272,-22.558 h3
  text ".GM2" at 41.423,-22.558 h3
M14-Top Assembly:
  text ".Layer_Name" at -0.272,-22.558 h3
  text ".GM14" at 41.423,-22.558 h3
M15-Bottom Assembly:
  text ".GM15" at 30.22,-22.59 h3
  text ".Layer_Name" at 71.534,-22.59 h3
Drill Drawing:
  drawing of 387 lines, arcs and shapes, not listed
  text "Layer" at 149.445,142.929 h2
  text "Name" at 157.814,142.929 h2
  text "Material" at 173.994,142.929 h2
  text "Thickness" at 188.538,142.929 h2
  text "Constant" at 200.483,142.929 h2
  text "Board Layer Stack" at 211.54,142.929 h2
  text "PCB : TYPE 3" at 232.476,141.738 h3
  text "Top Overlay" at 157.814,138.929 h2
  text "« THE COMPONENTS WITH PLATED THROUGH HOLE (PTH) MAY BE WELDED (CABLED) IN \"PIN-IN-PASTE\" MODE (IF NECESSARY) »" at 16.925,136.875 h3.5
  text "ASPECT-RATIO, AXE Z :" at 232.476,136.238 h3
  text "Top Solder" at 157.814,134.929 h2
  text "Solder Resist" at 173.994,134.929 h2
  text "0.015mm" at 188.538,134.929 h2
  text "3.5" at 200.483,134.929 h2
  text "1" at 149.445,130.929 h2
  text "Top Layer" at 157.814,130.929 h2
  text "0.035mm" at 188.538,130.929 h2
  text "PCB SPECIFICATIONS :" at 0.67,130.815 h3
  text "**Plating type :" at 117.72,130.465 h2.5
  text "6:1 to 8:1 / LEVEL \"B\"" at 232.495,129.49 h3
  text "Dielectric 1" at 157.814,126.929 h2
  text "0.108mm" at 188.538,126.929 h2
  text "4.2" at 200.483,126.929 h2
  text "A.   MATERIAL :" at 0.67,126.815 h3
  text "FR-4" at 39.17,126.815 h3
  text "TG-170" at 55.67,126.815 h3
  text "X  TG-150" at 73.92,126.815 h3
  text "TG-140" at 89.92,126.815 h3
  text "lead Gold" at 124.445,125.99 h2.5
  text "B.   MATERIAL FAMILY :" at 0.67,123.815 h3
  text "N/A" at 39.17,123.815 h3
  text "2" at 149.444,122.929 h2
  text "Signal Layer 1" at 157.814,122.929 h2
  text "0.035mm" at 188.538,122.929 h2
  text "C.   SOLDERMASK COLOR :" at 0.67,120.815 h3
  text "GREEN" at 39.17,120.815 h3
  text "X  WHITE" at 55.67,120.815 h3
  text "RED" at 73.92,120.815 h3
  text "BLACK" at 89.92,120.815 h3
  text "MINIMUM PARAMETERS" at 232.72,120.365 h3
  text "Dielectric 2" at 157.814,118.929 h2
  text "FR4" at 173.994,118.929 h2
  text "1.134mm" at 188.538,118.929 h2
  text "4.2" at 200.483,118.929 h2
  text "D.   SILKSCREEN COLOR :" at 0.67,117.815 h3
  text "WHITE" at 39.17,117.815 h3
  text "YELLOW" at 55.67,117.815 h3
  text "BLACK" at 73.92,117.815 h3
  text "X  Blue ink PANTONE 2955" at 89.92,117.815 h3
  text "3" at 149.445,114.929 h2
  text "Signal Layer 2" at 157.814,114.929 h2
  text "0.035mm" at 188.538,114.929 h2
  text "DEFAULT" at 232.72,114.865 h3
  text "E.   SURFACE FINISH :" at 0.67,114.815 h3
  text "X  ENIG" at 39.17,114.815 h3
  text "IMMERSION SILVER" at 55.67,114.815 h3
  text "IMMERSION TIN" at 89.92,114.815 h3
  text "HASL" at 39.17,111.815 h3
  text "HASL (PB-FREE)" at 55.67,111.815 h3
  text "GOLDEN FINGER" at 89.92,111.815 h3
  text "Dielectric 3" at 157.814,110.929 h2
  text "0.108mm" at 188.538,110.929 h2
  text "4.2" at 200.483,110.929 h2
  text "TRACKS : 0.120mm           / GAPS : 0.120mm" at 232.72,109.115 h3
  text "F.   IMPEDANCE CONTROL :" at 0.67,108.815 h3
  text "NO" at 39.17,108.815 h3
  text "X  YES  (SEE IMPEDANCE TABLE FOR DETAIL INFORMATION)" at 55.67,108.815 h3
  text "4" at 149.445,106.929 h2
  text "Bottom Layer" at 157.814,106.929 h2
  text "0.035mm" at 188.538,106.929 h2
  text "G.   THROUGH VIA :" at 0.67,105.815 h3
  text "PLUG THE VIAS WHICH ARE COVERED WITH SOLDERMASK ONE OR TWO SIDE." at 39.17,105.815 h3
  text "Bottom Solder" at 157.814,102.929 h2
  text "Solder Resist" at 173.994,102.929 h2
  text "0.015mm" at 188.538,102.929 h2
  text "3.5" at 200.483,102.929 h2
  text "PLUG MATERIAL :" at 39.17,102.815 h3
  text "X  SOLDERMASK" at 64.67,102.815 h3
  text "NON-CONDUCTIVE EPOXY." at 89.92,102.815 h3
  text "H.   STACK-UP :" at 0.67,99.815 h3
  text "SEE LAYER STACK-UP SEQUENCE FOR OVERALL THICKNESS." at 39.17,99.815 h3
  text "Bottom Overlay" at 157.814,98.929 h2
  text "Symbol" at 146.66,83.395 h2.4
  text "Count" at 156.053,83.395 h2.4
  text "Hole Size" at 165.794,83.395 h2.4
  text "Plated" at 185.044,83.395 h2.4
  text "Hole Type" at 193.292,83.395 h2.4
  text "Drill Layer Pair" at 205.295,83.395 h2.4
  text "Via/Pad" at 228.046,83.395 h2.4
  text "Hole Length" at 237.883,83.395 h2.4
  text "Routed Path Length" at 256.138,83.395 h2.4
  text "796" at 156.053,79.255 h2
  text "0.250mm (9.84mil)" at 165.794,79.255 h2
  text "PTH" at 185.044,79.255 h2
  text "Round" at 193.292,79.255 h2
  text "Top Layer - Bottom Layer" at 205.295,79.255 h2
  text "Via" at 228.046,79.255 h2
  text "-" at 237.883,79.255 h2
  text "-" at 256.138,79.255 h2
  text "8" at 156.053,75.114 h2
  text "0.500mm (19.69mil)" at 165.794,75.114 h2
  text "PTH" at 185.044,75.114 h2
  text "Slot" at 193.292,75.114 h2
  text "Top Layer - Bottom Layer" at 205.295,75.114 h2
  text "Pad" at 228.046,75.114 h2
  text "1.100mm (43.31mil)" at 237.883,75.114 h2
  text "0.600mm (23.62mil)" at 256.138,75.114 h2
  text "2" at 156.053,70.973 h2
  text "0.650mm (25.59mil)" at 165.794,70.973 h2
  text "NPTH" at 185.044,70.973 h2
  text "Round" at 193.292,70.973 h2
  text "Top Layer - Bottom Layer" at 205.295,70.973 h2
  text "Pad" at 228.046,70.973 h2
  text "-" at 237.883,70.973 h2
  text "-" at 256.138,70.973 h2
  text "2" at 156.053,66.833 h2
  text "0.650mm (25.59mil)" at 165.794,66.833 h2
  text "NPTH" at 185.044,66.833 h2
  text "Slot" at 193.292,66.833 h2
  text "Top Layer - Bottom Layer" at 205.295,66.833 h2
  text "Pad" at 228.046,66.833 h2
  text "0.950mm (37.40mil)" at 237.883,66.833 h2
  text "0.300mm (11.81mil)" at 256.138,66.833 h2
  text "2" at 156.053,62.692 h2
  text "0.970mm (38.19mil)" at 165.794,62.692 h2
  text "NPTH" at 185.044,62.692 h2
  text "Round" at 193.292,62.692 h2
  text "Top Layer - Bottom Layer" at 205.295,62.692 h2
  text "Pad" at 228.046,62.692 h2
  text "-" at 237.883,62.692 h2
  text "-" at 256.138,62.692 h2
  text "2" at 156.053,58.551 h2
  text "1.000mm (39.37mil)" at 165.794,58.551 h2
  text "NPTH" at 185.044,58.551 h2
  text "Round" at 193.292,58.551 h2
  text "Top Layer - Bottom Layer" at 205.295,58.551 h2
  text "Pad" at 228.046,58.551 h2
  text "-" at 237.883,58.551 h2
  text "-" at 256.138,58.551 h2
  text "137" at 156.053,54.411 h2
  text "1.000mm (39.37mil)" at 165.794,54.411 h2
  text "PTH" at 185.044,54.411 h2
  text "Round" at 193.292,54.411 h2
  text "Top Layer - Bottom Layer" at 205.295,54.411 h2
  text "Pad" at 228.046,54.411 h2
  text "-" at 237.883,54.411 h2
  text "-" at 256.138,54.411 h2
  text "2" at 156.053,50.27 h2
  text "1.190mm (46.85mil)" at 165.794,50.27 h2
  text "NPTH" at 185.044,50.27 h2
  text "Round" at 193.292,50.27 h2
  text "Top Layer - Bottom Layer" at 205.295,50.27 h2
  text "Pad" at 228.046,50.27 h2
  text "-" at 237.883,50.27 h2
  text "-" at 256.138,50.27 h2
  text "3" at 156.053,46.13 h2
  text "3.200mm (125.98mil)" at 165.794,46.13 h2
  text "NPTH" at 185.044,46.13 h2
  text "Round" at 193.292,46.13 h2
  text "Top Layer - Bottom Layer" at 205.295,46.13 h2
  text "Pad" at 228.046,46.13 h2
  text "-" at 237.883,46.13 h2
  text "-" at 256.138,46.13 h2
  text "954 Total" at 156.053,41.989 h2
  text "Slot definitions :" at 146.66,39.091 h2
  text "Routed Path Length" at 160.294,39.091 h2
  text "= Calculated from tool start centre position to tool end centre position." at 177.184,39.091 h2
  text "Hole Length" at 160.294,37.434 h2
  text "= Routed Path Length + Tool Size = Slot length as defined in the PCB layout" at 170.916,37.434 h2
  text ".Layer_Name" at -0.272,-22.558 h3
  text ".DRL" at 41.423,-22.558 h3
M20-Top Sheet Box:
  circle w0.254: c77.733,-29.279 r1.3
  region: 63.255,-30.372 52.499,-30.372 53.492,-27.879 61.35,-27.879 61.798,-27.12 64.007,-29.668
  region: 77.258,-22.042 61.731,-22.042 61.036,-23.818 59.826,-25.043 58.429,-23.183 58.429,-21.532 59.572,-20.135 61.008,-19.756 77.258,-19.756
  lines w0.254: 53.492,-27.879 62.284,-27.879 59.218,-24.341 cw(c61.021,-22.397) 61.262,-19.756 78.026,-19.756 77.264,-22.042 ; 56.806,-19.509 cw(c59.232,-20.48) 59.468,-17.877 ; 56.845,-19.477 52.499,-30.372 71.821,-30.372 ccw(c72.07,-27.637) 74.619,-28.657 ; 58.585,-23.411 64.007,-29.668 ; 58.839,-23.411 64.144,-29.533 ; 58.839,-23.157 64.144,-29.279 ; 58.937,-22.042 71.93,-22.042 ; 58.966,-23.03 64.271,-29.152 ; 59.093,-22.903 64.398,-29.025 ; 59.22,-22.776 64.525,-28.898 ; 59.347,-22.649 64.652,-28.771 ; 59.401,-20.697 64.706,-26.818 ; 59.47,-17.877 78.919,-17.877 74.62,-28.655 ; 59.474,-22.522 64.724,-28.581 ; 59.474,-22.268 64.779,-28.39 ; 59.474,-22.014 64.779,-28.136 ; 59.474,-21.125 64.779,-27.247 ; 59.601,-21.887 64.906,-28.009 ; 59.601,-21.506 64.906,-27.628 ; 60.972,-27.892 ccw(c61.077,-27.357) 61.375,-26.9 ; 62.059,-22.029 ccw(c62.033,-22.596) 61.703,-23.058 64.067,-25.787 cw(c62.264,-27.731) 62.996,-30.279 ; 68.34,-30.168 71.229,-21.788 ; 68.562,-30.118 71.432,-21.797 ; 68.689,-30.118 71.559,-21.797 ; 68.943,-30.118 71.813,-21.797 ; 69.197,-30.118 72.067,-21.797 ; 69.451,-30.118 72.321,-21.797 ; 69.705,-30.118 72.575,-21.797 ; 69.959,-30.118 72.829,-21.797 ; 70.213,-30.118 73.083,-21.797 ; 70.467,-30.118 73.337,-21.797 ; 70.676,-30.168 73.565,-21.788 ; 73.565,-22.042 77.258,-22.042 ; 76.59,-22.04 77.352,-19.754 ; 76.756,-22.042 77.518,-19.756 ; 77.01,-22.042 77.772,-19.756
  lines w0.3: -9.272,-29.258 50.728,-29.258 ; -9.272,-24.258 50.728,-24.258 ; -9.272,-19.258 50.728,-19.258 ; 30.728,-34.258 30.728,-19.258 ; 50.728,-34.258 50.728,-14.258 ; 68.34,-30.168 70.676,-30.168 ; -9.272,-34.258 80.728,-34.258 80.728,-14.258 -9.272,-14.258 -9.271,-34.258
  text "Project: '.Board_Name'" at -8.272,-17.474 h3
  text "Layer:" at -8.271,-22.558 h3
  text "Gerber:" at 31.717,-22.558 h3
  text "Variant: '.VariantName'" at -8.272,-27.558 h3
  text "'.Board_Reference'" at 31.844,-27.558 h3
  text "R" at 77.225,-30.041 h1.52
  text "Date: '.Board_Document_Date'" at -8.272,-32.558 h3
  text "Rev: '.Board_PCB_Revision'" at 31.787,-32.558 h3
M21-Bottom Sheet Box:
  circle w0.254: c-6.089,-29.279 r1.3
  region: -5.614,-22.042 9.913,-22.042 10.607,-23.818 11.818,-25.043 13.215,-23.183 13.215,-21.532 12.072,-20.135 10.636,-19.756 -5.614,-19.756
  region: 8.389,-30.372 19.145,-30.372 18.152,-27.879 10.294,-27.879 9.845,-27.12 7.637,-29.668
  lines w0.254: -6.128,-19.756 -5.366,-22.042 ; -5.874,-19.756 -5.112,-22.042 ; -5.708,-19.754 -4.946,-22.04 ; -5.62,-22.042 -6.382,-19.756 10.382,-19.756 cw(c10.622,-22.397) 12.426,-24.341 9.36,-27.879 18.152,-27.879 ; -5.614,-22.042 -1.922,-22.042 ; -2.976,-28.655 -7.276,-17.877 12.174,-17.877 ; -2.975,-28.657 ccw(c-0.426,-27.637) -0.178,-30.372 19.145,-30.372 14.799,-19.477 ; -1.922,-21.788 0.968,-30.168 ; -1.693,-21.797 1.176,-30.118 ; -1.439,-21.797 1.43,-30.118 ; -1.185,-21.797 1.684,-30.118 ; -0.931,-21.797 1.938,-30.118 ; -0.677,-21.797 2.192,-30.118 ; -0.423,-21.797 2.446,-30.118 ; -0.286,-22.042 12.707,-22.042 ; -0.169,-21.797 2.7,-30.118 ; 0.085,-21.797 2.954,-30.118 ; 0.212,-21.797 3.081,-30.118 ; 0.414,-21.788 3.304,-30.168 ; 6.738,-28.009 12.043,-21.887 ; 6.738,-27.628 12.043,-21.506 ; 6.865,-28.39 12.17,-22.268 ; 6.865,-28.136 12.17,-22.014 ; 6.865,-27.247 12.17,-21.125 ; 6.92,-28.581 12.17,-22.522 ; 6.937,-26.818 12.242,-20.697 ; 6.992,-28.771 12.297,-22.649 ; 7.119,-28.898 12.424,-22.776 ; 7.246,-29.025 12.551,-22.903 ; 7.373,-29.152 12.678,-23.03 ; 7.5,-29.533 12.805,-23.411 ; 7.5,-29.279 12.805,-23.157 ; 7.637,-29.668 13.059,-23.411 ; 8.647,-30.279 cw(c9.38,-27.731) 7.576,-25.787 9.941,-23.058 ccw(c9.611,-22.596) 9.585,-22.029 ; 10.269,-26.9 ccw(c10.566,-27.357) 10.671,-27.892 ; 12.175,-17.877 cw(c12.412,-20.48) 14.838,-19.509
  lines w0.3: 0.968,-30.168 3.304,-30.168 ; 20.728,-34.258 20.728,-14.258 ; 20.728,-29.258 80.728,-29.258 ; 20.728,-24.258 80.728,-24.258 ; 20.728,-19.258 80.728,-19.258 ; 40.728,-34.258 40.728,-19.258 ; -9.272,-34.258 -9.272,-14.258 80.728,-14.258 80.728,-34.258 -9.272,-34.258
  text "Project: '.Board_Name'" at 79.534,-17.474 h3
  text "Gerber:" at 39.545,-22.558 h3
  text "Layer:" at 79.534,-22.558 h3
  text "'.Board_Reference'" at 39.545,-27.558 h3
  text "Variant: '.VariantName'" at 79.534,-27.558 h3
  text "R" at -5.581,-30.041 h1.52
  text "Rev: '.Board_PCB_Revision'" at 39.602,-32.558 h3
  text "Date: '.Board_Document_Date'" at 79.534,-32.558 h3

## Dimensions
0,80.5 to 70,80.5 on M2-Board Dimensions
2,82.5 to 13.5,0 on M2-Board Dimensions
10.87,54.57 to 59.13,53.3 on M2-Board Dimensions
0,80.5 to 10.87,54.57 on M2-Board Dimensions
59.13,53.3 to 70,80.5 on M2-Board Dimensions
10.87,54.57 to 2,82.5 on M2-Board Dimensions
10.87,54.57 to 43.89,2.5 on M2-Board Dimensions
59.13,53.3 to 43.89,2.5 on M2-Board Dimensions
3.25,5.04 to 66.75,5.04 on M2-Board Dimensions
3.25,5.04 to 10.87,5.04 on M2-Board Dimensions
10.87,5.04 to 59.13,5.04 on M2-Board Dimensions
59.13,5.04 to 66.75,5.04 on M2-Board Dimensions
3.25,50.76 to 10.87,54.57 on M2-Board Dimensions
10.87,54.57 to 10.87,40.6 on M2-Board Dimensions
10.87,40.6 to 10.87,17.74 on M2-Board Dimensions
59.13,53.3 to 64.21,50.76 on M2-Board Dimensions
59.13,53.3 to 59.13,26.884 on M2-Board Dimensions
59.13,26.884 to 59.13,5.04 on M2-Board Dimensions
43.89,2.5 to 59.13,5.04 on M2-Board Dimensions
